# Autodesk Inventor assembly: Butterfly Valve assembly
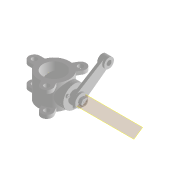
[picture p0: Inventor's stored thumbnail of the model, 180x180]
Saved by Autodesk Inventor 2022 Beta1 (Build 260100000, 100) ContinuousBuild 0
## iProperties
Created: 2019-03
Part Number: Butterfly Valve assembly
Document SubType Name: Assembly
Designer: LENOVO-CADCIM
Author: LENOVO-CADCIM
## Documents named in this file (10)
- D:\PROJECTS_2021\Resources\Tutorial Files\c09_Inv_2022_tut\c09_Inv_2021_tut\c09_Inv_tut_2021\c09_tut01_inv\Butterfly Valve\Butterfly Valve assembly.iam
- D:\PROJECTS_2021\Resources\Tutorial Files\c09_Inv_2022_tut\c09_Inv_2021_tut\c09_Inv_tut_2021\c09_tut01_inv\Butterfly Valve\Body.ipt
- D:\PROJECTS_2021\Resources\Tutorial Files\c09_Inv_2022_tut\c09_Inv_2021_tut\c09_Inv_tut_2021\c09_tut01_inv\Butterfly Valve\Shaft.ipt
- D:\PROJECTS_2021\Resources\Tutorial Files\c09_Inv_2022_tut\c09_Inv_2021_tut\c09_Inv_tut_2021\c09_tut01_inv\Butterfly Valve\Retainer.ipt
- D:\PROJECTS_2021\Resources\Tutorial Files\c09_Inv_2022_tut\c09_Inv_2021_tut\c09_Inv_tut_2021\c09_tut01_inv\Butterfly Valve\Arm.ipt
- D:\PROJECTS_2021\Resources\Tutorial Files\c09_Inv_2022_tut\c09_Inv_2021_tut\c09_Inv_tut_2021\c09_tut01_inv\Butterfly Valve\Plate.ipt
- D:\PROJECTS_2021\Resources\Tutorial Files\c09_Inv_2022_tut\c09_Inv_2021_tut\c09_Inv_tut_2021\c09_tut01_inv\Butterfly Valve\scew1.ipt
- D:\PROJECTS_2021\Resources\Tutorial Files\c09_Inv_2022_tut\c09_Inv_2021_tut\c09_Inv_tut_2021\c09_tut01_inv\Butterfly Valve\Screw.ipt
- D:\PROJECTS_2021\Resources\Tutorial Files\c09_Inv_2022_tut\c09_Inv_2021_tut\c09_Inv_tut_2021\c09_tut01_inv\Butterfly Valve\Parallel key.ipt
- D:\PROJECTS_2021\Resources\Tutorial Files\c09_Inv_2022_tut\c09_Inv_2021_tut\c09_Inv_tut_2021\c09_tut01_inv\Butterfly Valve\Nut.ipt
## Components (12 placed, 9 different names)
1. Body:1 — Insert:1, Insert:2, Mate:1, Angle:4, Angle:5
2. Shaft:1 — Insert:1, Insert:3, Insert:4, Mate:3, Insert:11, Angle:5
3. Retainer:1 — Insert:2, Mate:1, Insert:7, Insert:8, Insert:9, Insert:10
4. Arm:1 — Insert:10, Mate:2, Flush:1
5. Plate:1 — Insert:3, Insert:4, Insert:5, Insert:6
6. scew1:1 — Insert:5
7. scew1:2 — Insert:6
8. Screw:1 — Insert:7
9. Screw:2 — Insert:8
10. Screw:3 — Insert:9
11. Parallel key:1 — Mate:2, Mate:3, Flush:1
12. Nut:1 — Insert:11, Angle:4
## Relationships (17: Insert 11, Mate 3, Angle 2, Flush 1)
- Insert:1: Body:1 ↔ Shaft:1
- Insert:2: Body:1 ↔ Retainer:1
- Mate:1: Body:1 ↔ Retainer:1
- Insert:3: Shaft:1 ↔ Plate:1
- Insert:4: Shaft:1 ↔ Plate:1
- Insert:5: Plate:1 ↔ scew1:1
- Insert:6: Plate:1 ↔ scew1:2
- Insert:7: Retainer:1 ↔ Screw:1
- Insert:8: Retainer:1 ↔ Screw:2
- Insert:9: Retainer:1 ↔ Screw:3
- Insert:10: Retainer:1 ↔ Arm:1
- Mate:2: Arm:1 ↔ Parallel key:1
- Mate:3: Shaft:1 ↔ Parallel key:1
- Flush:1: Arm:1 ↔ Parallel key:1
- Insert:11: Shaft:1 ↔ Nut:1
- Angle:4: Body:1 ↔ Nut:1
- Angle:5: Body:1 ↔ Shaft:1
